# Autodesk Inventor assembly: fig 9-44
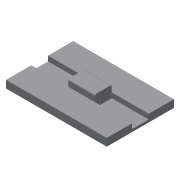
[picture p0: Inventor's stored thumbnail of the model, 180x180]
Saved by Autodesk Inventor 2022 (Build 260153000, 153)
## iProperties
Created: 2013-07
Part Number: fig 9-44
Document SubType Name: Assembly
Designer: CADCIM
Author: CADCIM
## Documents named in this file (3)
- D:\PROJECTS_2021\Resources\Part Files\c09_Inv_2022_prt\fig 9-45.iam
- D:\PROJECTS_2021\Resources\Part Files\c09_Inv_2022_prt\15.ipt
- D:\PROJECTS_2021\Resources\Part Files\c09_Inv_2022_prt\16.ipt
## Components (2 placed, 2 different names)
1. 15:1 — Slider:1
2. 16:1 — Slider:1
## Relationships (1: TranslationJoint 1)
- Slider:1 [TranslationJoint]: 15:1 ↔ 16:1
